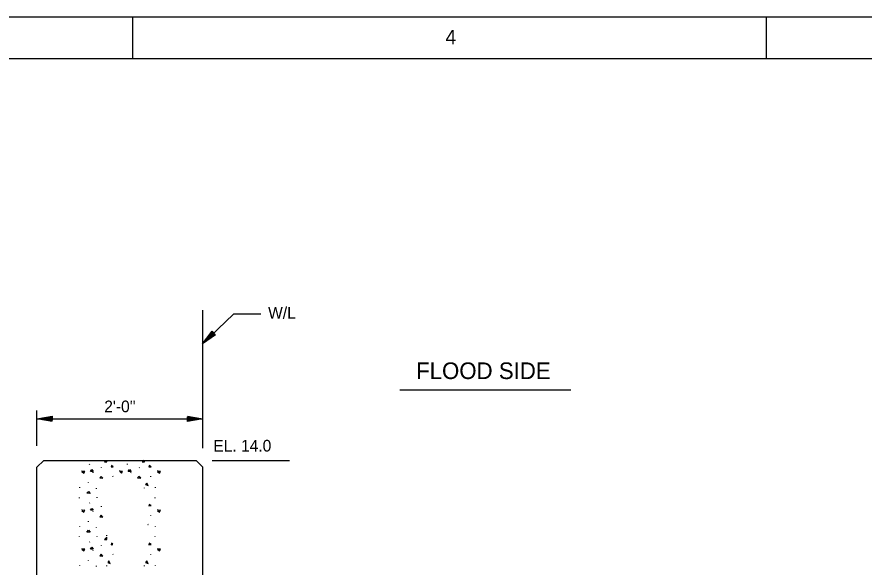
# Model space of a CAD drawing. Extents: x 0 to 320, y -4 to 473.
# Drawn here: x 7.61 to 17.8, y 21.38 to 28 of the extents above; entities that cross this region are included whole.
import ezdxf

# ---------------------------------------------------------------- set-up
doc = ezdxf.new("R2010")
doc.units = 0
for name, color, linetype in [('Level 1', 7, 'Continuous'), ('Level 10', 7, 'Continuous'), ('Level 2', 7, 'Continuous'), ('Level 3', 7, 'Continuous'), ('Level 50', 7, 'Continuous')]:
    doc.layers.add(name, color=color, linetype=linetype)

msp = doc.modelspace()

# ---------------------------------------------------------------- linework, layer by layer
at = {"layer": 'Level 1'}
for p, q in [((9, 27.5), (9, 28)), ((16.625, 27.5), (16.625, 28))]:
    msp.add_line(p, q, dxfattribs=at)
for points in [[(0, 28), (40, 28), (40, 0), (0, 0)], [(1.5, 27.5), (39.5, 27.5), (39.5, 0.5), (1.5, 0.5)]]:
    msp.add_lwpolyline(points, close=True, dxfattribs=at)
at = {"layer": 'Level 10'}
for p, q in [((8.388, 22.539), (8.389, 22.544)), ((8.478, 22.619), (8.481, 22.624)), ((8.623, 22.577), (8.624, 22.583)), ((8.844, 22.539), (8.844, 22.544)), ((8.934, 22.619), (8.936, 22.624)), ((9.078, 22.577), (9.079, 22.583)), ((9.299, 22.539), (9.3, 22.544)), ((8.521, 22.518), (8.524, 22.523)), ((8.762, 22.469), (8.759, 22.475)), ((8.977, 22.518), (8.98, 22.523)), ((9.218, 22.469), (9.215, 22.475)), ((8.361, 22.338), (8.362, 22.343)), ((8.467, 22.397), (8.467, 22.402)), ((8.564, 22.326), (8.562, 22.332)), ((9.141, 22.331), (9.141, 22.337)), ((9.272, 22.338), (9.273, 22.343)), ((8.357, 22.214), (8.357, 22.22)), ((8.478, 22.151), (8.481, 22.156)), ((8.57, 22.218), (8.569, 22.223)), ((9.268, 22.214), (9.268, 22.22)), ((8.388, 22.071), (8.389, 22.076)), ((8.521, 22.051), (8.524, 22.056)), ((8.623, 22.109), (8.624, 22.115)), ((9.299, 22.071), (9.3, 22.076)), ((8.467, 21.929), (8.467, 21.934)), ((9.218, 22.002), (9.215, 22.007)), ((8.361, 21.871), (8.362, 21.875)), ((8.564, 21.858), (8.562, 21.865)), ((9.272, 21.871), (9.273, 21.875)), ((8.357, 21.746), (8.357, 21.752)), ((8.57, 21.751), (8.569, 21.755)), ((8.688, 21.76), (8.688, 21.766)), ((9.268, 21.746), (9.268, 21.752)), ((8.478, 21.684), (8.481, 21.689)), ((8.623, 21.642), (8.624, 21.648)), ((8.388, 21.604), (8.389, 21.608)), ((8.521, 21.583), (8.524, 21.588)), ((8.762, 21.534), (8.759, 21.54)), ((9.218, 21.534), (9.215, 21.54)), ((9.299, 21.604), (9.3, 21.608)), ((8.467, 21.462), (8.467, 21.467)), ((8.361, 21.403), (8.362, 21.408)), ((8.564, 21.391), (8.562, 21.397)), ((8.685, 21.396), (8.685, 21.402)), ((9.141, 21.396), (9.141, 21.402)), ((9.272, 21.403), (9.273, 21.408))]:
    msp.add_line(p, q, dxfattribs=at)
for points in [[(8.675, 22.667), (8.657, 22.649), (8.686, 22.651)], [(8.686, 22.651), (8.687, 22.667)], [(9.131, 22.667), (9.112, 22.649), (9.141, 22.651)], [(9.141, 22.651), (9.142, 22.667)], [(8.638, 21.985), (8.619, 22.007), (8.602, 21.987), (8.638, 21.983)], [(9.181, 21.897), (9.183, 21.896), (9.181, 21.901)], [(8.758, 21.66), (8.743, 21.67), (8.739, 21.653)], [(8.739, 21.653), (8.76, 21.655)]]:
    msp.add_lwpolyline(points, dxfattribs=at)
for points in [[(8.387, 22.532), (8.409, 22.512), (8.421, 22.535)], [(8.489, 22.535), (8.505, 22.557), (8.524, 22.535)], [(8.739, 22.588), (8.764, 22.591), (8.743, 22.605)], [(8.842, 22.532), (8.864, 22.512), (8.876, 22.535)], [(8.944, 22.535), (8.961, 22.557), (8.98, 22.535)], [(9.194, 22.588), (9.22, 22.591), (9.198, 22.605)], [(9.298, 22.532), (9.32, 22.512), (9.332, 22.535)], [(8.639, 22.451), (8.619, 22.474), (8.602, 22.455)], [(9.095, 22.451), (9.074, 22.474), (9.058, 22.455)], [(9.154, 22.375), (9.183, 22.364), (9.168, 22.394)], [(8.447, 22.272), (8.466, 22.293), (8.488, 22.269)], [(9.194, 22.12), (9.22, 22.124), (9.198, 22.138)], [(8.387, 22.065), (8.409, 22.045), (8.421, 22.067)], [(8.489, 22.067), (8.505, 22.089), (8.524, 22.068)], [(9.298, 22.065), (9.32, 22.045), (9.332, 22.067)], [(8.447, 21.804), (8.466, 21.826), (8.488, 21.802)], [(8.686, 21.716), (8.688, 21.744), (8.657, 21.714)], [(8.489, 21.599), (8.505, 21.622), (8.524, 21.6)], [(9.194, 21.653), (9.22, 21.656), (9.198, 21.67)], [(8.387, 21.597), (8.409, 21.577), (8.421, 21.599)], [(8.639, 21.515), (8.619, 21.539), (8.602, 21.519)], [(9.298, 21.597), (9.32, 21.577), (9.332, 21.599)], [(8.699, 21.439), (8.727, 21.428), (8.712, 21.459)], [(9.154, 21.439), (9.183, 21.428), (9.168, 21.459)]]:
    msp.add_lwpolyline(points, close=True, dxfattribs=at)
at = {"layer": 'Level 2'}
for p, q in [((7.844, 23.167), (9.844, 23.167)), ((7.927, 22.667), (9.761, 22.667)), ((7.844, 13.834), (7.844, 22.584)), ((9.844, 14.167), (9.844, 22.584))]:
    msp.add_line(p, q, dxfattribs=at)
at = {"layer": 'Level 3'}
for p, q in [((9.844, 22.813), (9.844, 24.473)), ((9.84, 24.067), (9.84, 24.067)), ((9.878, 24.104), (9.878, 24.104)), ((12.215, 23.515), (14.271, 23.515)), ((7.844, 22.841), (7.844, 23.265)), ((7.927, 22.667), (7.844, 22.584)), ((9.761, 22.667), (9.844, 22.584)), ((9.954, 22.667), (10.884, 22.667))]:
    msp.add_line(p, q, dxfattribs=at)
for points in [[(10.542, 24.427), (10.21, 24.427), (9.84, 24.067)], [(9.996, 24.176), (9.84, 24.067), (9.953, 24.22), (9.99, 24.182), (9.878, 24.104), (9.954, 24.207), (9.978, 24.183), (9.913, 24.138), (9.955, 24.194), (9.965, 24.184), (9.951, 24.175)]]:
    msp.add_lwpolyline(points, dxfattribs=at)
at = {"layer": 'Level 50'}
for p, q in [((7.844, 23.167), (7.844, 23.167)), ((7.896, 23.167), (7.896, 23.167)), ((9.792, 23.167), (9.792, 23.167)), ((9.844, 23.167), (9.844, 23.167))]:
    msp.add_line(p, q, dxfattribs=at)
for points in [[(8.031, 23.136), (7.844, 23.167), (8.031, 23.198), (8.031, 23.145), (7.896, 23.167), (8.023, 23.188), (8.023, 23.154), (7.946, 23.167), (8.015, 23.178), (8.015, 23.164), (7.998, 23.167)], [(9.657, 23.198), (9.844, 23.167), (9.657, 23.136), (9.657, 23.189), (9.792, 23.167), (9.665, 23.146), (9.665, 23.18), (9.742, 23.167), (9.673, 23.156), (9.673, 23.17), (9.69, 23.167)]]:
    msp.add_lwpolyline(points, dxfattribs=at)

# ---------------------------------------------------------------- texts
at = {"layer": 'Level 1'}
msp.add_text('4', height=0.175, dxfattribs=at).set_placement((12.762, 27.67))
at = {"layer": 'Level 10'}
msp.add_text('EL. 14.0', height=0.14, dxfattribs=at).set_placement((9.969, 22.773))
at = {"layer": 'Level 3'}
for s, height, p in [('W/L', 0.14, (10.628, 24.371)), ('FLOOD SIDE', 0.2, (12.409, 23.645)), ("2'-0''", 0.14, (8.656, 23.246))]:
    msp.add_text(s, height=height, dxfattribs=at).set_placement(p)

doc.saveas('drawing.dxf')
